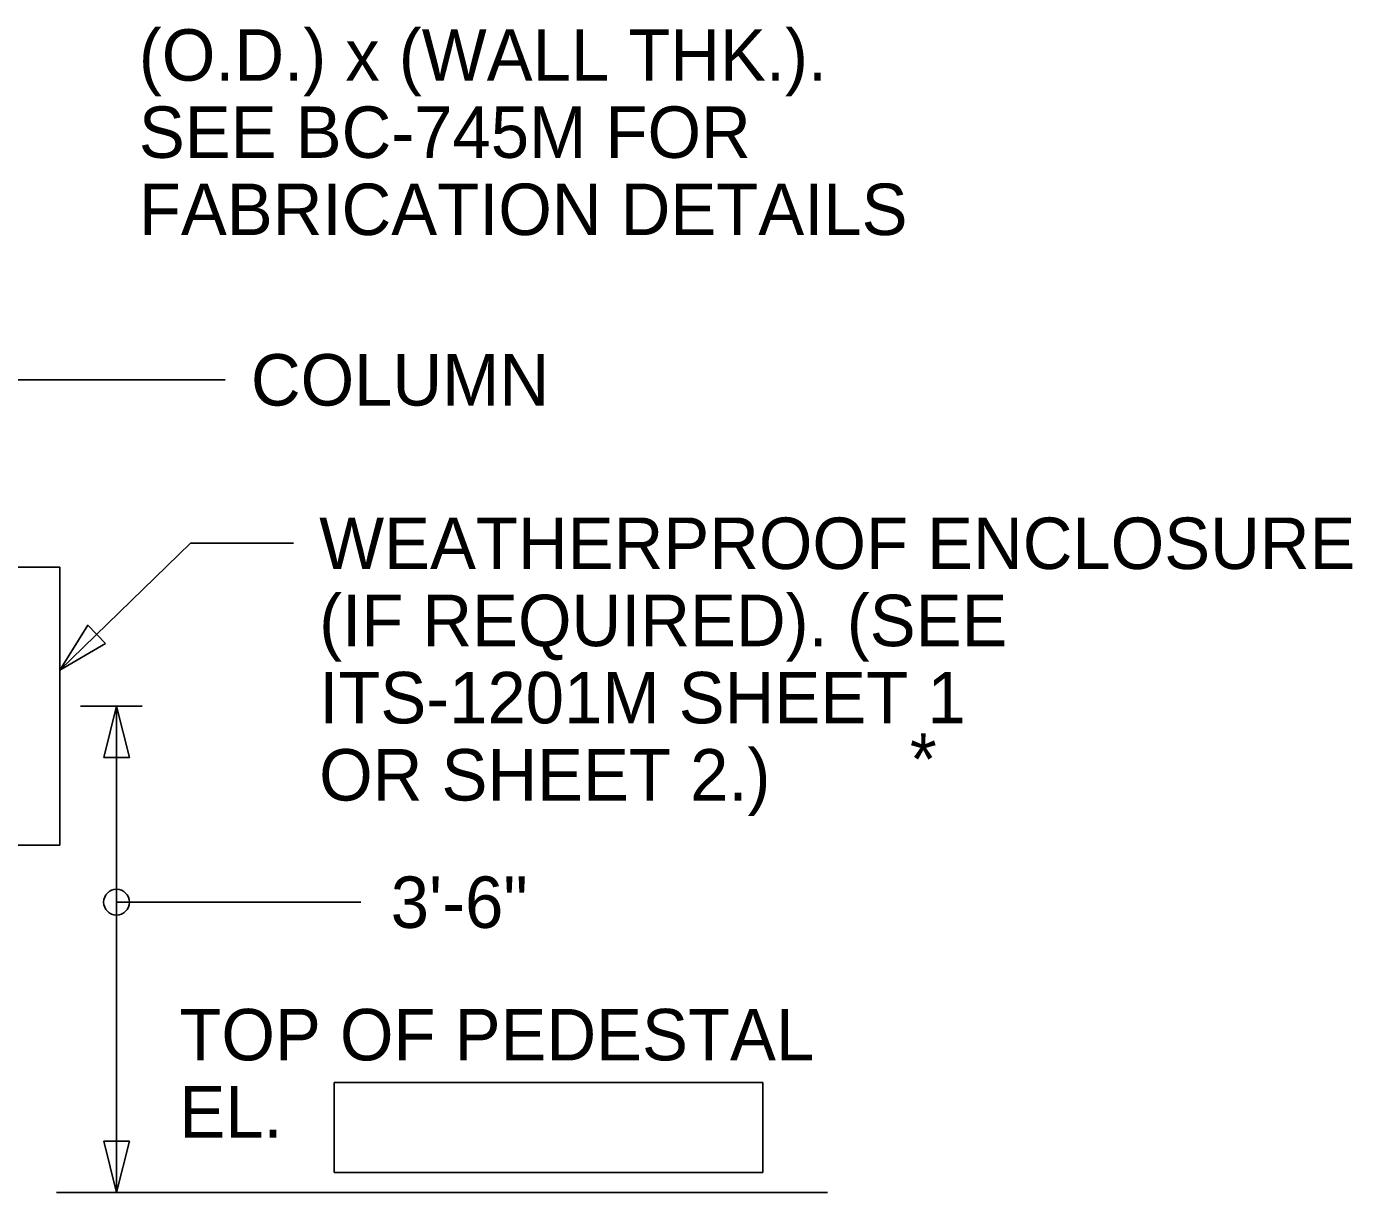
# Model space of a CAD drawing. Extents: x 3831399 to 3833095, y 499014 to 500202.
# Drawn here: x 3832754.1 to 3832829, y 499800 to 499865.9 of the extents above; entities that cross this region are included whole.
import ezdxf

# ---------------------------------------------------------------- set-up
doc = ezdxf.new("R2010")
doc.units = 0
for name, color, linetype in [('0-DEVICE ATTACH', 7, 'Continuous'), ('Default', 7, 'Continuous'), ('DIM TXT', 7, 'Continuous')]:
    doc.layers.add(name, color=color, linetype=linetype)

msp = doc.modelspace()

# ---------------------------------------------------------------- linework, layer by layer
at = {"layer": '0-DEVICE ATTACH'}
for p, q in [((3832755.948, 499835.355), (3832751.022, 499835.355)), ((3832755.948, 499819.631), (3832755.948, 499835.355)), ((3832751.022, 499819.631), (3832755.948, 499819.631))]:
    msp.add_line(p, q, dxfattribs=at)
at = {"layer": 'Default'}
for p, q in [((3832771.457, 499806.208), (3832795.706, 499806.208)), ((3832771.457, 499801.115), (3832771.457, 499806.208)), ((3832795.706, 499806.208), (3832795.706, 499801.115)), ((3832795.706, 499801.115), (3832771.457, 499801.115)), ((3832755.765, 499799.987), (3832799.363, 499799.987))]:
    msp.add_line(p, q, dxfattribs=at)
at = {"layer": 'DIM TXT'}
for p, q in [((3832749.64, 499845.955), (3832759.482, 499845.949)), ((3832765.302, 499845.949), (3832759.482, 499845.949)), ((3832755.948, 499829.524), (3832763.341, 499836.706)), ((3832769.161, 499836.706), (3832763.341, 499836.706)), ((3832757.123, 499827.495), (3832760.613, 499827.495)), ((3832758.431, 499824.585), (3832759.158, 499827.495)), ((3832759.158, 499799.987), (3832759.158, 499827.495)), ((3832759.158, 499827.495), (3832759.885, 499824.585)), ((3832759.885, 499824.585), (3832758.431, 499824.585)), ((3832772.965, 499816.407), (3832759.158, 499816.407)), ((3832759.158, 499799.987), (3832758.431, 499802.897)), ((3832758.431, 499802.897), (3832759.885, 499802.897)), ((3832759.885, 499802.897), (3832759.158, 499799.987)), ((3832757.22, 499799.987), (3832760.613, 499799.987))]:
    msp.add_line(p, q, dxfattribs=at)
msp.add_lwpolyline([(3832758.542, 499831.03), (3832755.948, 499829.524), (3832757.528, 499832.073)], close=True, dxfattribs=at)
msp.add_circle((3832759.157, 499816.407), 0.727, dxfattribs=at)

# ---------------------------------------------------------------- texts
for s, height, p in [('(O.D.) x (WALL THK.).', 2.90992, (3832760.421, 499862.87)), ('SEE BC-745M FOR', 2.90992, (3832760.421, 499858.505)), ('FABRICATION DETAILS', 2.90992, (3832760.421, 499854.14)), ('COLUMN', 2.9099, (3832766.757, 499844.495)), ('WEATHERPROOF ENCLOSURE', 2.90992, (3832770.616, 499835.251)), ('(IF REQUIRED). (SEE', 2.90992, (3832770.616, 499830.886)), ('ITS-1201M SHEET 1', 2.90992, (3832770.616, 499826.521)), ('*', 2.91, (3832804.015, 499823.045)), ('OR SHEET 2.)', 2.90992, (3832770.616, 499822.156)), ('3\'-6"', 2.9099, (3832774.661, 499814.952)), ('TOP OF PEDESTAL', 2.90992, (3832762.71, 499807.46)), ('EL.', 2.9099, (3832762.71, 499803.095))]:
    msp.add_text(s, height=height, dxfattribs=at).set_placement(p)

doc.saveas('drawing.dxf')
